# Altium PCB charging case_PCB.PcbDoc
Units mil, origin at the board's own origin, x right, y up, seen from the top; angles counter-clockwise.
Board outline 2230 x 2230 mil, 2 copper layers (Top Layer, Bottom Layer), stack 62 mil thick; 58 components, 44 nets, 186 pads, 33 vias.
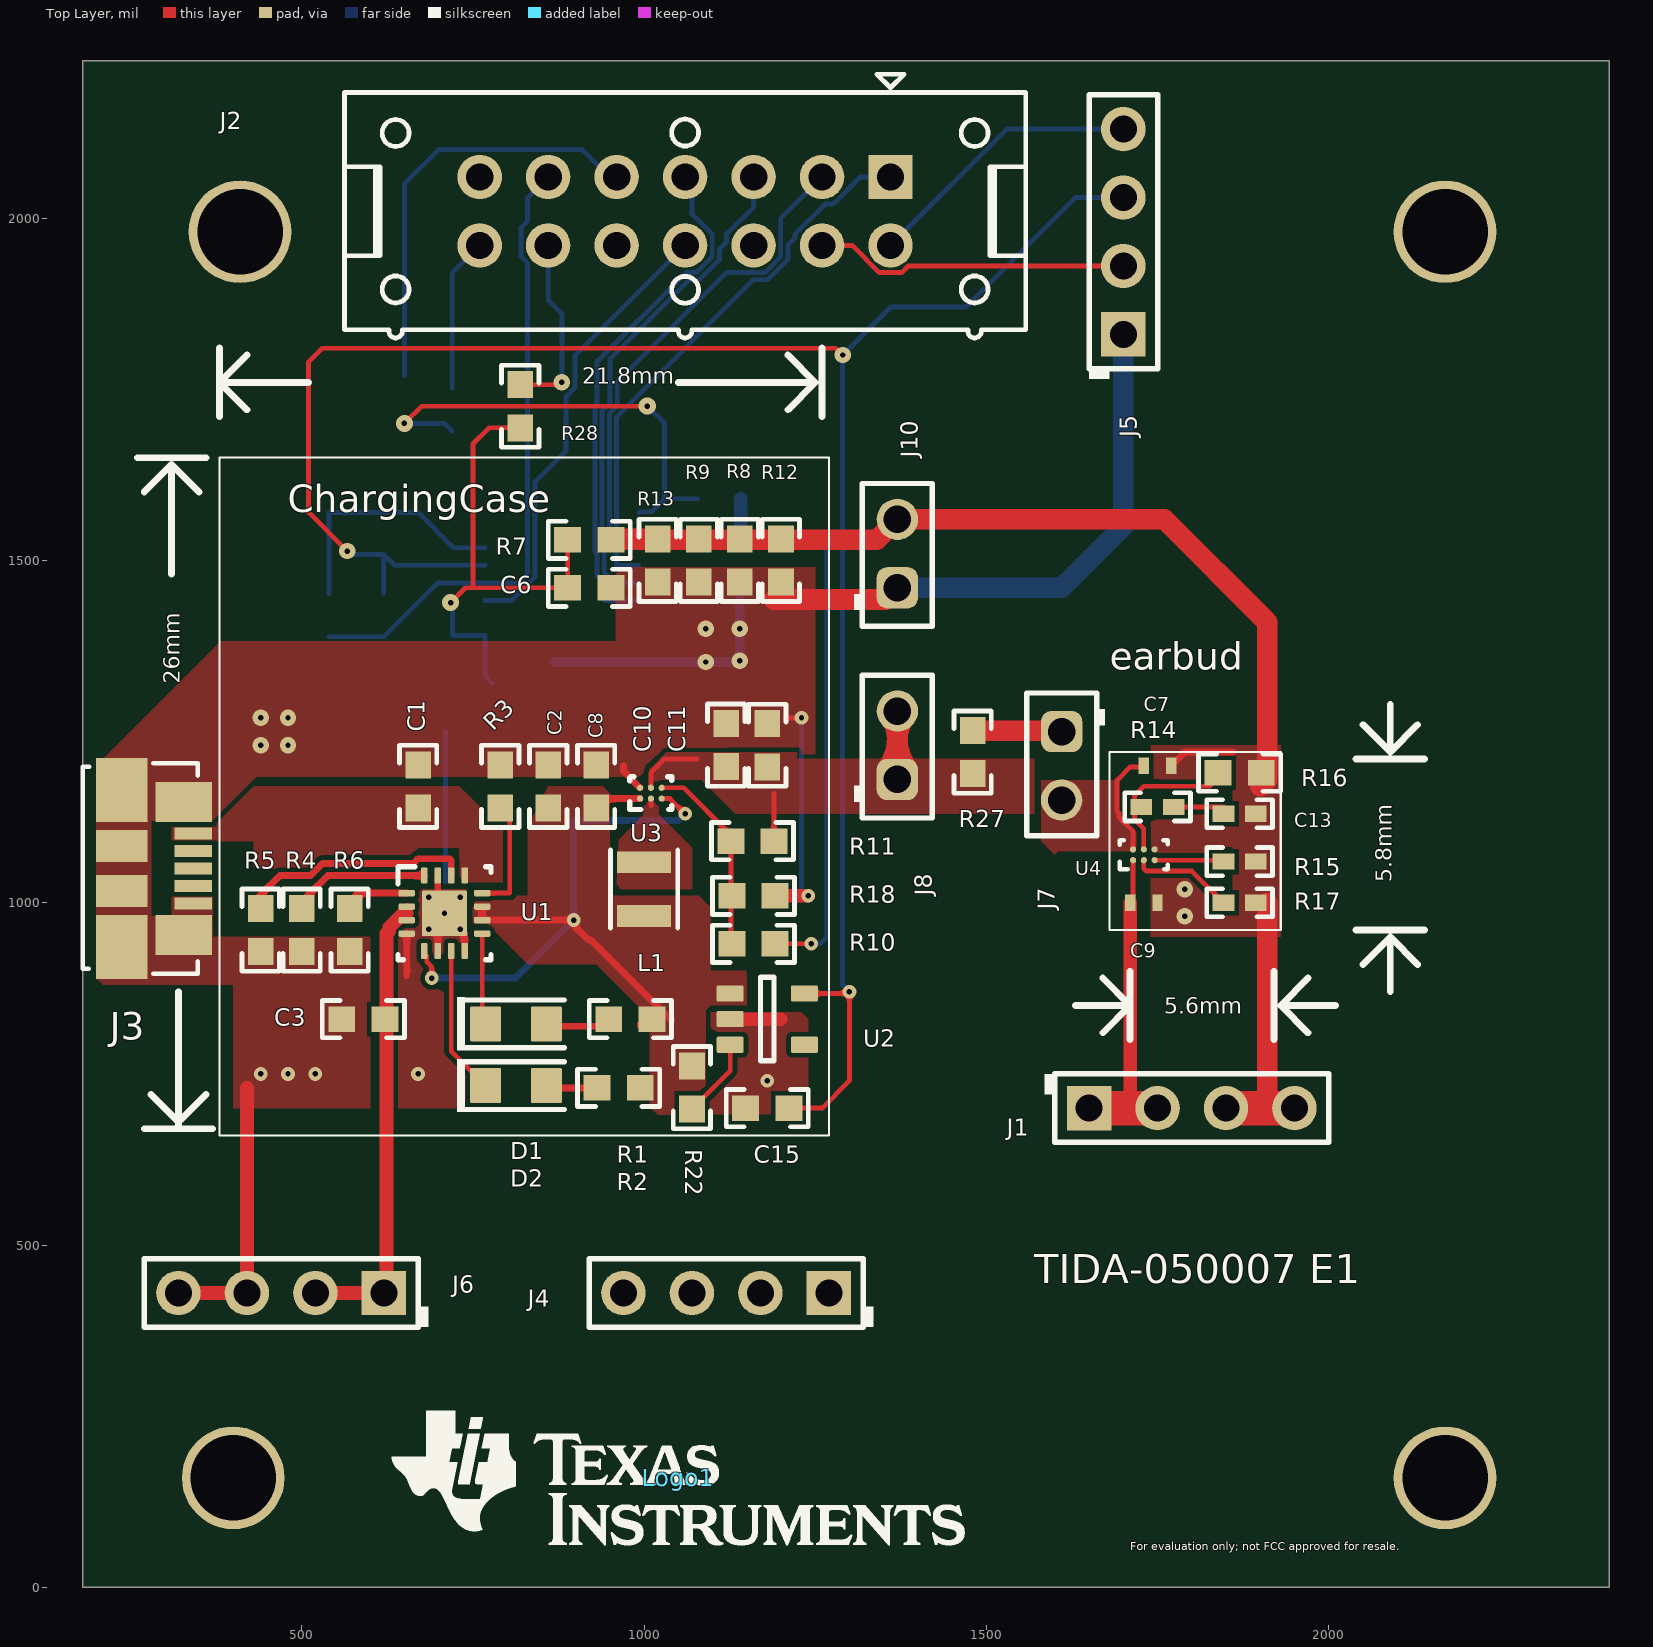
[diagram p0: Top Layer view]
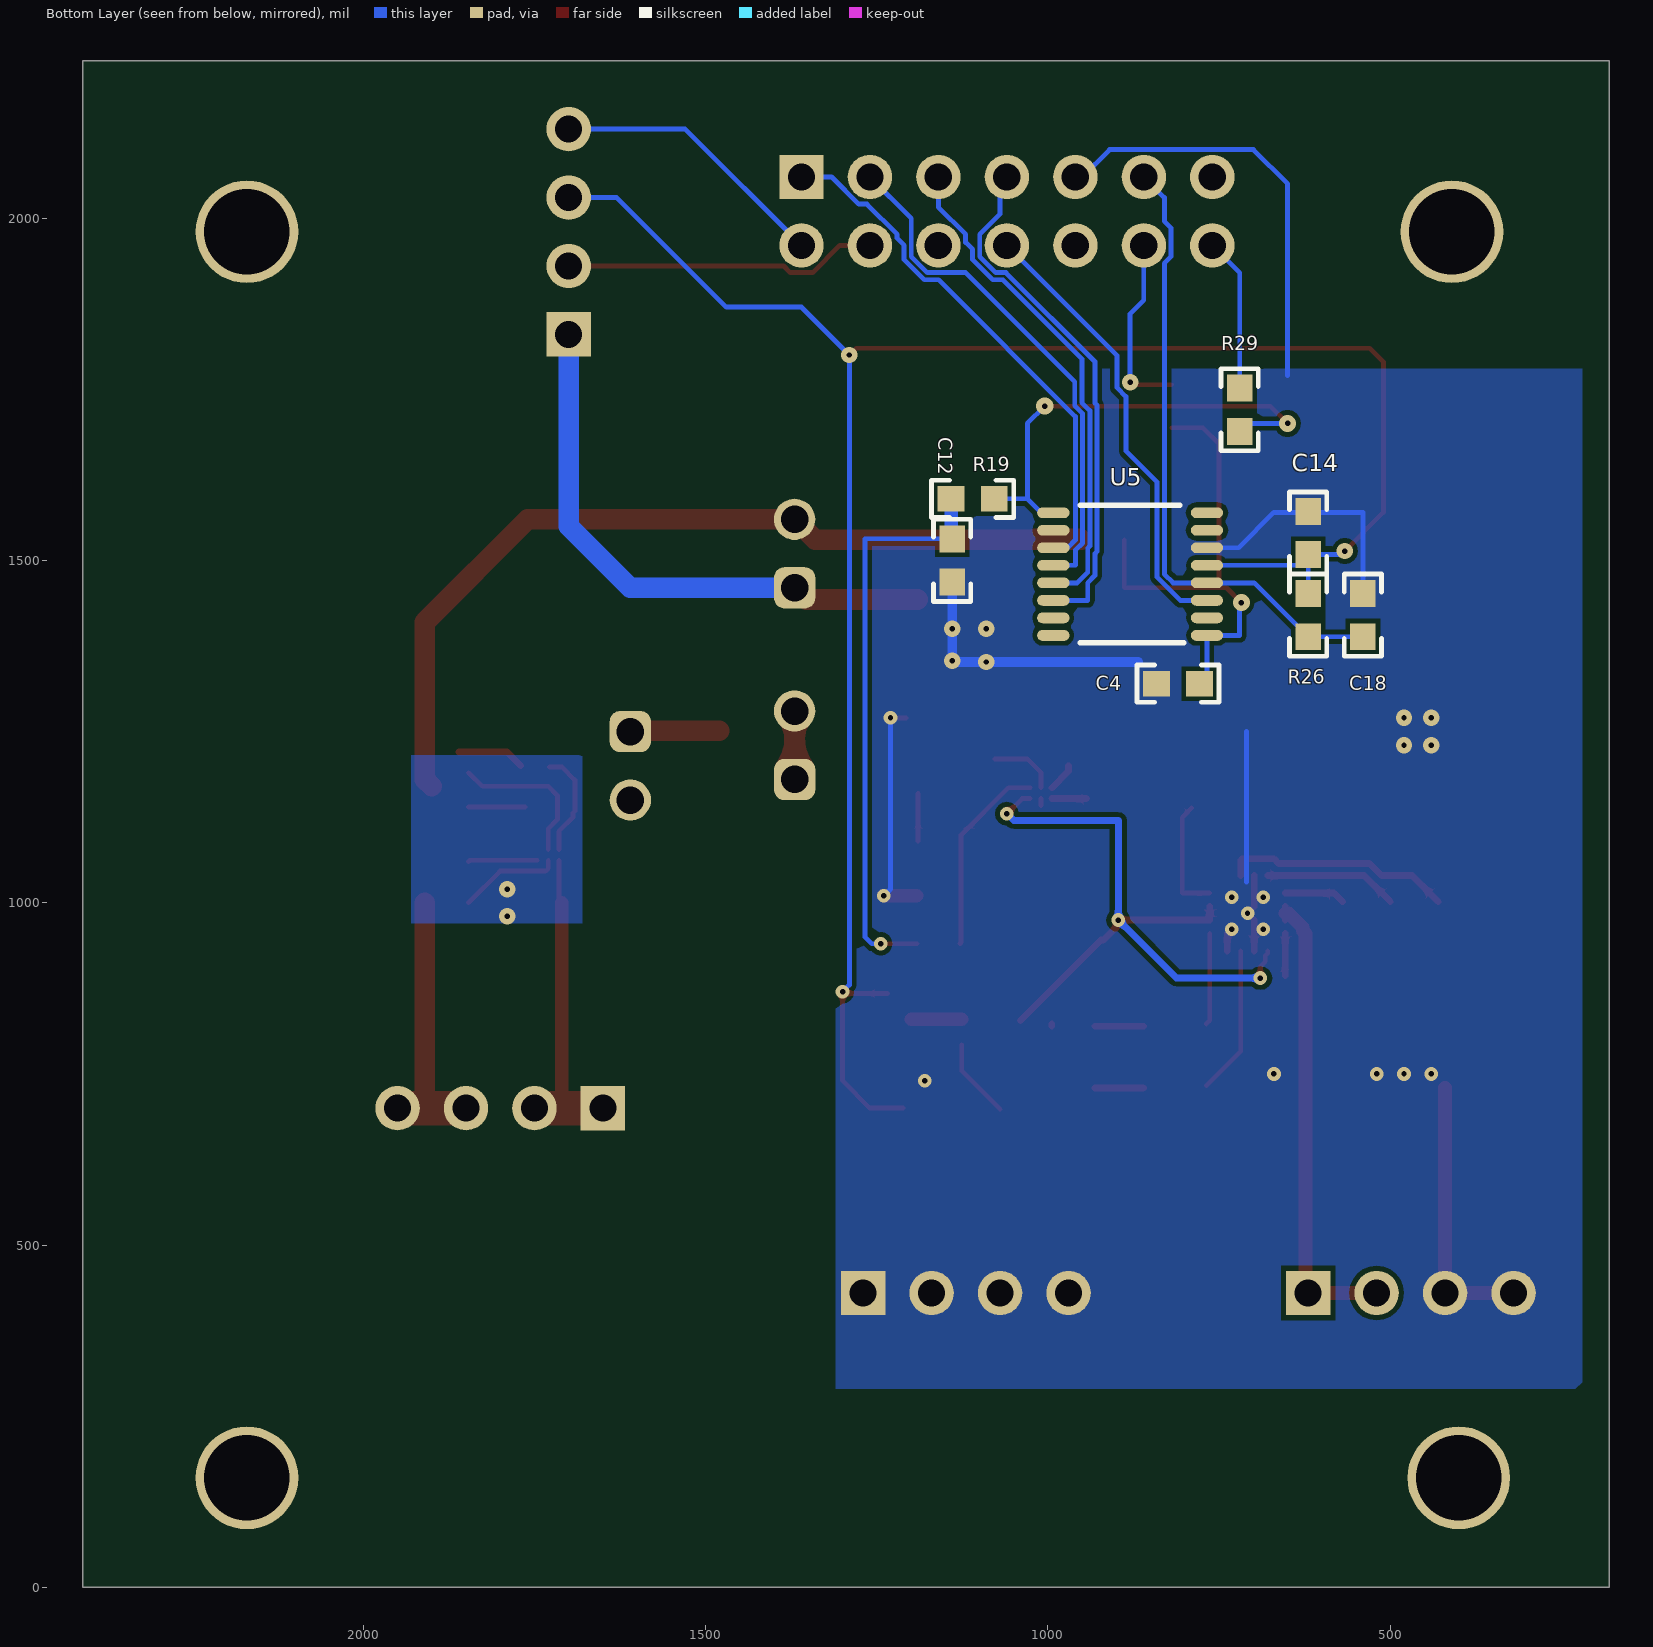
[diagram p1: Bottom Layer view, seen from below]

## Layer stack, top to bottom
Top Solder: solder mask 0.4, Solder Resist, Dk 3.5
Top Layer: signal copper 1.4
Dielectric1: core 59.2, FR-4, Dk 4.8
Bottom Layer: signal copper 1.4
Bottom Solder: solder mask 0.4, Solder Resist, Dk 3.5

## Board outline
180,0 2410,0 2410,2230 180,2230

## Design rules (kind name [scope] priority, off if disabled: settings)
AcuteAngle [All] p1: minimum=4.50000000000000E+0001 checktracksonly=FALSE
AssemblyTestPointUsage [All] p1: valid=2
Clearance Clearance_Keepouts [((IsTrack Or IsArc) And Not InPoly) And IsFree and IsKeepOut vs ((IsTrack Or IsArc) And Not InPoly) And IsFree and IsKeepOut] p1: gap=0 ignorepadtopadclearanceinfootprint=FALSE
Clearance Clearance_Poly [InPolygon] p2: gap=7 ignorepadtopadclearanceinfootprint=FALSE except(0: Arc-Hole Track-Hole SMDPad-Hole THPad-Hole Via-Hole Fill-Hole Poly-Hole Region-Hole Text-Hole)
Clearance Clearance_FiducialMark [IsKeepOut and InComponentClass('FiducialMark') vs IsPad and InComponentClass('FiducialMark')] p3: gap=0 ignorepadtopadclearanceinfootprint=FALSE
Clearance [All] p4: gap=3.6 ignorepadtopadclearanceinfootprint=FALSE except(0: Arc-Hole Track-Hole SMDPad-Hole THPad-Hole Via-Hole Fill-Hole Poly-Hole Region-Hole Text-Hole)
ComponentClearance ComponentClearance_MountingHoles_FiducialMarks [InComponentClass('Mounting Holes') vs InComponentClass('FiducialMark')] p1: gap=50 collisioncheckmode=3 verticalgap=10 showdistances=FALSE
ComponentClearance ComponentClearance_Shunt [InComponentClass('Header') vs InComponentClass('Shunt')] p2: gap=0 collisioncheckmode=3 verticalgap=0 showdistances=FALSE
ComponentClearance ComponentClearance_Logo [InComponentClass('Logo')] p3: gap=50 collisioncheckmode=3 verticalgap=10 showdistances=FALSE
ComponentClearance ComponentClearance_ScrewToNut [(HasFootprint('NY PMS 440 0025 PH')) vs (HasFootprint('Keystone_1902C'))] p4: gap=5 collisioncheckmode=3 verticalgap=10 showdistances=FALSE
ComponentClearance ComponentClearance_MountingHoles [InComponentClass('Mounting Holes')] p5: gap=250 collisioncheckmode=3 verticalgap=100000 showdistances=FALSE
ComponentClearance ComponentClearance_SmallPassives [HasFootprint('0201*') or HasFootprint('0402*') or HasFootprint('0508') or HasFootprint('0603*') or HasFootprint('0612') or HasFootprint('0805*') or HasFootprint('0815*') or HasFootprint('0830*') or HasFootprint('1206*') or HasFootprint('1210*') or HasFootprint('1808*') or HasFootprint('1812*') or HasFootprint('1825*') or HasFootprint('2010*') or HasFootprint('2220*') or HasFootprint('2225*') or HasFootprint('2512*') or HasFootprint('2728*') or HasFootprint('3518*') vs HasFootprint('0201*') or HasFootprint('0402*') or HasFootprint('0508') or HasFootprint('0603*') or HasFootprint('0612') or HasFootprint('0805*') or HasFootprint('0815*') or HasFootprint('0830*') or HasFootprint('1206*') or HasFootprint('1210*') or HasFootprint('1808*') or HasFootprint('1812*') or HasFootprint('1825*') or HasFootprint('2010*') or HasFootprint('2220*') or HasFootprint('2225*') or HasFootprint('2512*') or HasFootprint('2728*') or HasFootprint('3518*')] p6: gap=14.96 collisioncheckmode=3 verticalgap=10 showdistances=FALSE
ComponentClearance ComponentClearance_THtoSMT [IsThruComponent vs IsSMTComponent] p7: gap=40 collisioncheckmode=3 verticalgap=30 showdistances=FALSE
ComponentClearance ComponentClearance_THtoTH [IsThruComponent vs IsThruComponent] p8: gap=30 collisioncheckmode=3 verticalgap=30 showdistances=FALSE
ComponentClearance [All] p9: gap=30 collisioncheckmode=3 verticalgap=10 showdistances=FALSE
DiffPairsRouting [All] p1: maxlimit=100 minlimit=10 mostfreqgap=10 toplayer_minwidth=15 toplayer_maxwidth=15 toplayer_prefwidth=15 bottomlayer_minwidth=15 bottomlayer_maxwidth=15 bottomlayer_prefwidth=15 maxuncoupledlength=1000
FabricationTestPointUsage TestPointUsage [All] p1: valid=2 allowmultiple=FALSE
FabricationTestpoint Testpoint [All] p1: side=3 testpointundercomponent=TRUE minsize=40 maxsize=100 preferedsize=60 minholesize=0 maxholesize=40 preferedholesize=32 testpointgrid=1 allowsidetop=TRUE allowsidebottom=TRUE usegrid=TRUE gridtolerance=0.01
FanoutControl Fanout_LCC [IsLCC] p1: bgadir=Out bgaviamode=Centered fanoutstyle=Auto fanoutdirection=Alternating viagrid=1 // Fanout_LCC (Default Rule)
FanoutControl Fanout_BGA [IsBGA] p2: bgadir=Out bgaviamode=Centered fanoutstyle=Auto fanoutdirection=Alternating viagrid=1 // Fanout_BGA (Default Rule)
FanoutControl Fanout_Default [All] p4: bgadir=Out bgaviamode=Centered fanoutstyle=Auto fanoutdirection=Alternating viagrid=1 // Fanout_Default (Default Rule)
FanoutControl Fanout_Small [(CompPinCount < 5)] p5: bgadir=Out bgaviamode=Centered fanoutstyle=Auto fanoutdirection=OutThenIn viagrid=1 // Fanout_Small (Default Rule)
HoleSize [All] p1: absolutevalues=TRUE maxlimit=251 minlimit=7.87 maxpercent=80.000 minpercent=20.000
MinimumAnnularRing MinimumAnnularRing_ThermalPadVias [IsVia and InAnyComponent] p1: minimumring=5.91
MinimumAnnularRing [All] p2: minimumring=6
MinimumSolderMaskSliver MinimumSolderMaskSliver_Logo [InComponentClass('Logo') vs InComponentClass('Logo')] p1: minsoldermaskwidth=0.7
MinimumSolderMaskSliver [All] p2: minsoldermaskwidth=3.44
PlaneClearance [All] p1: clearance=0
PlaneConnect [All] p1: planeconnectstyle=Direct reliefexpansion=10 reliefentries=4 reliefconductorwidth=10 reliefairgap=10
PolygonConnect [All] p1: connectstyle=Direct reliefconductorwidth=10 reliefentries=4 polygonreliefangle="90 Angle" airgapwidth=10
RoutingVias ThermalPadVias [IsVia and InAnyComponent] p1: holewidth=7.87 width=19.68 viastyle="Through Hole" minholewidth=7.87 minwidth=19.68 maxholewidth=12.99 maxwidth=23.62
RoutingVias [All] p2: holewidth=16 width=34 viastyle="Through Hole" minholewidth=6 minwidth=20 maxholewidth=40 maxwidth=65
SilkToBoardRegionClearance [Not ((IsComment or IsDesignator) And (Hide <> 'False')) and not InRegion(1000,500,4000,800)] p1:
SilkToSilkClearance SilkToSilkClearance_Pb-FreeLogo [(HasFootprint('Pb-Free_Overlay_Medium') OR HasFootprint('Pb-Free_Overlay_Small')) vs (HasFootprint('Pb-Free_Overlay_Medium') OR HasFootprint('Pb-Free_Overlay_Small'))] p1: silktosilkclearance=0
SilkToSilkClearance [All] p2: silktosilkclearance=4
SilkToSolderMaskClearance SilkToComponentPadClearance [(IsPad or IsFill or IsRegion) and InAnycomponent] p1: minsilkscreentomaskgap=5 clearancetoexposedcopper=TRUE
SilkToSolderMaskClearance "Silk to Solder Mask Opening" [All] p2: minsilkscreentomaskgap=4 clearancetoexposedcopper=FALSE
SolderMaskExpansion [All] p1: expansion=1.97
UnpouredPolygon [All] p1: allowunpoured=TRUE
Width [All] p1: maxlimit=100 minlimit=6 preferedwidth=7 checkconnectedcopper=TRUE
13 further rules are at their usual default settings.

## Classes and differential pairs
component class Logo: Logo1
component class "charging case_EVM_Hardware": Logo1 Logo3
component class Header: J1 J4 J5 J6 J7 J8 J10

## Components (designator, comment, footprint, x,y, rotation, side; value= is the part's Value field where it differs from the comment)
C1 "GRM188Z71A106MA73D" 0603 670,1170 r90 top value=10uF
C2 "GRM188Z71A106MA73D" 0603 860.18,1170 r90 top value=10uF
C3 "GRM188Z71A106MA73D" 0603 590,830 r180 top value=10uF
C4 "GRM1885C1E102JA01D" 0603 810,1320 r0 bottom value=1000pF
C6 "06033D104KAT2A" 0603 920,1460 r180 top value=0.1uF
C7 "C1005X5R0J106M050BC" 0402_070 1750,1200 r180 top value=10uF
C8 "GRM188Z71A106MA73D" 0603 930,1170 r90 top value=10uF
C9 "C1005X5R0J106M050BC" 0402_070 1730,1000 r0 top value=10uF
C10 "06033D104KAT2A" 0603 1120,1230.2 r90 top value=0.1uF
C11 "GRM188Z71A106MA73D" 0603 1180,1230 r90 top value=10uF
C12 "06033D104KAT2A" 0603 1140,1500 r270 bottom value=0.1uF
C13 "GRM155R61E104KA87D" 0402 1870,1130 r0 top value=0.1uF
C14 "GRM188Z71A106MA73D" 0603 620,1540 r90 bottom value=10uF
C15 "GRM188Z71A106MA73D" 0603 1180,700 r180 top value=10uF
C18 "GRM1885C1E102JA01D" 0603 540,1420 r90 bottom value=1000pF
D1 "BR1112H-TR" BR1112H_Red 813,823 r180 top value=Red
D2 "BR1112H-TR" BR1112H_Red 813,733 r180 top value=Red
J1 "5-146278-4" TE_5-146278-4 1800,700 r0 top
J2 "SBH11-PBPC-D07-ST-BK" CONN_SBH11-PBPC-D07-ST-BK 1060,2010 r180 top
J3 "473460001" CONN_47346-0001 180,1050 r90 top
J4 "5-146278-4" TE_5-146278-4 1120,430 r180 top
J5 "5-146278-4" TE_5-146278-4 1700,1980 r90 top
J6 "5-146278-4" TE_5-146278-4 470,430 r180 top
J7 "TSW-102-17-G-S" Samtec_TSW-102-17-x-S 1610,1200 r270 top
J8 "TSW-102-17-G-S" Samtec_TSW-102-17-x-S 1370,1230 r90 top
J10 "TSW-102-17-G-S" Samtec_TSW-102-17-x-S 1370,1510 r90 top
L1 "DFE252012F-2R2M=P2" DFE252012C 1000,1020 r90 top value=2.2uH
Logo1 "Texas Instruments" TI_Stacked_Overlay_Small 1050,160 r0 top
Logo3 "FCC disclaimer" FCC_disclaimer 2570,120 r0 top
R1 "RT0603DRE07549RL" 0603 980,830 r180 top value=549
R2 "RT0603DRE07549RL" 0603 963,729.57 r180 top value=549
R3 "RC0603FR-073K09L" 0603 790,1170 r270 top value=3.09k
R4 "RC0603FR-074K32L" 0603 500,960 r90 top value=4.32k
R5 "RC0603FR-0756K2L" 0603 440,960 r90 top value=56.2k
R6 "RC0603FR-0710KL" 0603 570,960 r90 top value=10.0k
R7 "RG1608P-204-B-T5" 0603 920,1530 r0 top value=200k
R8 "RC0603FR-072RL" 0603 1140,1500 r270 top value=2.00
R9 "RC0603FR-072RL" 0603 1080,1500 r270 top value=2.00
R10 "RT0603DRE07255KL" 0603 1160,940 r180 top value=255k
R11 "MCT06030C1004FP500" 0603 1158.33,1090 r0 top value=1.00Meg
R12 "RC0603FR-072RL" 0603 1200,1500 r270 top value=2.00
R13 "RC0603FR-072RL" 0603 1019.76,1500 r270 top value=2.00
R14 "RC0402FR-07180KL" 0402 1750,1140 r180 top value=180k
R15 "RC0402FR-076K81L" 0402 1870,1060 r180 top value=6.81k
R16 "RC0603JR-071KL" 0603 1870,1190 r180 top value=1.0k
R17 "RC0402FR-0710KL" 0402 1870,1000 r180 top value=10.0k
R18 "RT0603DRE07348KL" 0603 1160,1010 r180 top value=348k
R19 "RC0603FR-07576KL" 0603 1110,1590 r0 bottom value=576k
R22 "RG1608P-204-B-T5" 0603 1070,730 r90 top value=200k
R26 "RT0603BRD0747K5L" 0603 620,1420 r90 bottom value=47.5k
R27 "RMCF0603ZT0R00" 0603 1480,1220 r90 top value=0
R28 "RMCF0603ZT0R00" 0603 819.29,1725.19 r90 top value=0
R29 "RMCF0603ZT0R00" 0603 720,1720 r90 bottom value=0
U1 "BQ24230RGTR" RGT0016C 708.57,984.5 r0 top
U2 "TPS7A0533PDBV" DBV0005A_N 1180,830 r0 top
U3 "TPS61099YFFR" YFF0006AFAD 1010,1160 r90 top
U4 "BQ25100AYFPR" YFP0006AFAV 1730,1070 r90 top
U5 "MSP430FR2111IPW16R" PW0016A_L 880,1480 r0 bottom

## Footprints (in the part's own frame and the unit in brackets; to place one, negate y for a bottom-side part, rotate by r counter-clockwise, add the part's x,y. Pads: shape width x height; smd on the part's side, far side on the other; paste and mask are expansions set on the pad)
0402 [mm] "0402 from SM-752 data"
  rect 0.8x0.6 smd: 1(-0.6,0) 2(0.6,0)
  silkscreen extent -1.22,-0.52 1.22,0.52, body extent -0.55,-0.3 0.55,0.3, height 0.6
0402_070 [mil] "SMD, 2-Leads, Body 1.2x0.7mm, Height 0.7mm"
  rect 15x24 smd: 1(-20,0) 2(20,0)
  body extent -24,-14 24,14, height 28
0603 [mm] "0603 from SM-752 data"
  rect 1x0.95 smd: 1(-0.8,0) 2(0.8,0)
  silkscreen extent -1.52,-0.69 1.52,0.69, body extent -0.87,-0.47 0.87,0.47, height 1
BR1112H_Red [mm] "SMD, 2-Leads, Body 2x1.25mm"
  rrect9% 1.15x1.3 smd: 1(-1.125,0) 2(1.125,0)
  silkscreen extent -1.79,-0.99 2.18,0.99, body extent -1,-0.63 1,0.62, height 0.79
CONN_47346-0001 [mm] "MOLEX"
  rect 0.45x1.38 smd: 1(1.3,-4.105) 2(0.65,-4.105) 3(0,-4.105) 4(-0.65,-4.105) 5(-1.3,-4.105)
  rect 1.475x2.1 smd: 6(-2.462,-3.755) 11(2.463,-3.75)
  rect 2.375x1.9 smd: 7(-2.912,-1.45) 10(2.912,-1.45)
  rect 1.175x1.9 smd: 8(-0.837,-1.45) 9(0.837,-1.45)
  silkscreen extent -3.9,-4.28 3.9,0, body extent -3.99,-4.43 3.99,1, height 2.72
CONN_SBH11-PBPC-D07-ST-BK [mm] "Sullins recommended land pattern"
  rect 1.65x1.65 hole 1.016 mask+0: 1(-7.62,-1.27)
  round 1.65 hole 1.016 mask+0: 2(-7.62,1.27) 3(-5.08,-1.27) 4(-5.08,1.27) 5(-2.54,-1.27) 6(-2.54,1.27) 7(0,-1.27) 8(0,1.27) 9(2.54,-1.27) 10(2.54,1.27) 11(5.08,-1.27) 12(5.08,1.27) 13(7.62,-1.27) 14(7.62,1.27)
  silkscreen extent -12.64,-5.08 12.64,4.7, body extent -12.64,-4.4 12.64,4.7, height 9.12
DBV0005A_N [mm] "SOT23, 5-Leads, Body 2.9x1.6mm, Pitch 0.95mm, Lead Span 2.8mm, IPC Medium Density"
  rrect17% 1x0.6 smd: 1(-1.375,0.95) 2(-1.375,0) 3(-1.375,-0.95) 4(1.375,-0.95) 5(1.375,0.95)
  silkscreen extent -0.25,-1.55 0.25,1.55, body extent -1.42,-1.46 1.42,1.46, height 1.09
DFE252012C [mm] "Toko"
  rect 0.8x2 smd: 1(-1,0) 2(1,0)
  silkscreen extent -1.45,-1.25 1.45,1.25, body extent -1.35,-1.1 1.35,1.1, height 1.2
FCC_disclaimer [mil]
PW0016A_L [mm] "TSOP, 16-Leads, Body 5x4.4mm, Pitch 0.65mm, IPC High Density"
  oval 1.2x0.4 smd: 1(-2.85,2.275) 2(-2.85,1.625) 3(-2.85,0.975) 4(-2.85,0.325) 5(-2.85,-0.325) 6(-2.85,-0.975) 7(-2.85,-1.625) 8(-2.85,-2.275) 9(2.85,-2.275) 10(2.85,-1.625) 11(2.85,-0.975) 12(2.85,-0.325) 13(2.85,0.325) 14(2.85,0.975) 15(2.85,1.625) 16(2.85,2.275)
  silkscreen extent -2,-2.55 1.85,2.55, body extent -3.21,-2.5 3.21,2.5, height 1
RGT0016C [mm] "QFN, 16-Leads, Body 3x3mm, Pitch 0.5mm, Thermal Pad 1.7x1.7mm, TI Recommended"
  rrect42% 0.6x0.24 smd: 1(-1.4,0.75) 2(-1.4,0.25) 3(-1.4,-0.25) 4(-1.4,-0.75) 9(1.4,-0.75) 10(1.4,-0.25) 11(1.4,0.25) 12(1.4,0.75)
  rrect42% 0.24x0.6 smd: 5(-0.75,-1.4) 6(-0.25,-1.4) 7(0.25,-1.4) 8(0.75,-1.4) 13(0.75,1.4) 14(0.25,1.4) 15(-0.25,1.4) 16(-0.75,1.4)
  rrect6% 1.55x1.55 on Top Paste: 17(0,0)
  rrect6% 1.68x1.68 smd paste-0.85: 17(0,0)
  silkscreen extent -1.72,-1.72 1.73,1.73, body extent -1.5,-1.5 1.5,1.5, height 1
Samtec_TSW-102-17-x-S [mm] "Header, 2.54mm, 2x1, TH"
  rrect50% 1.53x1.53 hole 1.02: 1(-1.27,0)
  round 1.53 hole 1.02: 2(1.27,0)
  silkscreen extent -2.7,-1.3 2.6,1.6, body extent -2.67,-1.27 2.54,1.27, height 18.29
TE_5-146278-4 [mm] "TE CONNECTIVITY"
  rect 1.65x1.65 hole 1: 1(-3.81,0)
  round 1.65 hole 1: 2(-1.27,0) 3(1.27,0) 4(3.81,0)
  silkscreen extent -5.46,-1.27 5.08,1.27, body extent -4.95,-1.17 4.95,1.17, height 8.13
TI_Stacked_Overlay_Small [mil]
  silkscreen extent -418,-98 418,98
YFF0006AFAD [mm] "DSBGA, 6-Leads, Body 1.226x 0.884mm, Pitch 0.4mm"
  round 0.23 smd paste-0.13 mask+0.038: A1(-0.2,0.4) A2(0.2,0.4) B1(-0.2,0) B2(0.2,0) C1(-0.2,-0.4) C2(0.2,-0.4)
  silkscreen extent -0.61,-0.78 0.61,0.78, body extent -0.46,-0.63 0.46,0.63, height 0.63
YFP0006AFAV [mm] "TI DSBGA 0.88x1.58mm"
  round 0.23 smd paste-0.13 mask+0.038: A1(-0.2,0.4) A2(0.2,0.4) B1(-0.2,0) B2(0.2,0) C1(-0.2,-0.4) C2(0.2,-0.4)
  silkscreen extent -0.53,-0.89 0.53,0.89, body extent -0.46,-0.8 0.46,0.81, height 0.51

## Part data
C1 C2 C3 C8 C11 C14 C15: library part CMP-0007497-5, "CAP, CERM, 10 uF, 10 V, +/- 20%, X7R, 0603", Cap_Case=0603, Manufacturer=MuRata, Supplier Part Number 1=81-GRM188Z71A106MA3D, TempCo=X7R, Tolerance_%=20%, Value1=Unknown, Value2=10V, ValueDisplayed=10uF
C4 C18: library part CMP-0007159-4, "CAP, CERM, 1000 pF, 25 V, +/- 5%, C0G/NP0, 0603", Cap_Case=0603, Manufacturer=MuRata, Supplier Part Number 1=GRM1885C1E102JA01D-ND, TempCo=C0G/NP0, Tolerance_%=5%, Value1=Unknown, Value2=25V, ValueDisplayed=1000pF
C6 C10 C12: library part CMP-0006758-5, "CAP, CERM, 0.1 uF, 25 V, +/- 10%, X5R, 0603", Cap_Case=0603, Manufacturer=AVX, Supplier Part Number 1=478-1244-1-ND, TempCo=X5R, Tolerance_%=10%, Value1="0.048 ohm", Value2=25V, ValueDisplayed=0.1uF
C7 C9: library part CMP-0006257-2, "CAP, CERM, 10 uF, 6.3 V, +/- 20%, X5R, 0402", Cap_Case=0402_070, Manufacturer=TDK, Supplier Part Number 1=445-8920-1-ND, TempCo=X5R, Tolerance_%=20%, Value1="0.003019 ohm", Value2=6.3V, ValueDisplayed=10uF
C13: library part CMP-0006607-2, "CAP, CERM, 0.1 uF, 25 V, +/- 10%, X5R, 0402", Cap_Case=0402, Manufacturer=MuRata, Supplier Part Number 1=490-5920-1-ND, TempCo=X5R, Tolerance_%=10%, Value1=Unknown, Value2=25V, ValueDisplayed=0.1uF
D1 D2: library part CMP-0067678-1, "LED, Red, SMD", Color=Red, Manufacturer="Stanley Electric Co., LTD", Power_TotalModule=57.5mW, Supplier Part Number 1=404-1017-1-ND, Value1=0.0575W, Value2=1.7V
J1 J4 J5 J6: library part CMP-0054950-1, "Header, 100mil, 4x1, Tin, TH", Manufacturer="TE Connectivity", Supplier Part Number 1=5-146278-4-ND
J2: library part CMP-0054695-1, "Header (shrouded), 100 mil, 7x2, Gold, TH", Manufacturer="Sullins Connector Solutions", Supplier Part Number 1=S9170-ND
J3: library part CMP-0055296-1, "Connector, Receptacle, Micro-USB Type B, R/A, Bottom Mount SMT", Manufacturer=Molex, Supplier Part Number 1=WM17141CT-ND
J7 J8 J10: library part CMP-0077742-1, "Header, 2.54mm, 2x1, Gold, TH", Color=Black, Manufacturer=Samtec, Supplier Part Number 1=SAM1061-02-ND
L1: library part CMP-0058932-1, "Inductor, Shielded, Powdered Iron, 2.2 uH, 2.3 A, 0.082 ohm, SMD", Manufacturer="MuRata Toko", PartNumber=DFE252012F-2R2M{}P2, Supplier Part Number 1=490-13055-1-ND, Value1="0.082 ohm", Value2=2.3A, ValueDisplayed=2.2uH
Logo1: library part CMP-0074838-1, "Texas Instrument Corporate Signature"
Logo3: library part CMP-0074847-1, "FCC_disclaimer"
R1 R2: library part CMP-0025400-3, "RES, 549, 0.5%, 0.1 W, 0603", Manufacturer="Yageo America", Power_W=100mW, TempCo="50 ppm/C", Tolerance_%=0.5%, Value2=0.1W, Value_Code=549R, ValueDisplayed=549
R3: library part CMP-0023077-3, "RES, 3.09 k, 1%, 0.1 W, 0603", Manufacturer="Yageo America", Power_W=100mW, Supplier Part Number 1=311-3.09KHRCT-ND, TempCo="200 ppm/C", Tolerance_%=1%, Value2=0.1W, Value_Code=3k09, ValueDisplayed=3.09k
R4: library part CMP-0023147-3, "RES, 4.32 k, 1%, 0.1 W, 0603", Manufacturer="Yageo America", Power_W=100mW, Supplier Part Number 1=311-4.32KHRCT-ND, TempCo="200 ppm/C", Tolerance_%=1%, Value2=0.1W, Value_Code=4k32, ValueDisplayed=4.32k
R5: library part CMP-0023186-3, "RES, 56.2 k, 1%, 0.1 W, 0603", Manufacturer="Yageo America", Power_W=100mW, Supplier Part Number 1=311-56.2KHRCT-ND, TempCo="200 ppm/C", Tolerance_%=1%, Value2=0.1W, Value_Code=56k2, ValueDisplayed=56.2k
R6: library part CMP-0022746-3, "RES, 10.0 k, 1%, 0.1 W, 0603", Manufacturer="Yageo America", Power_W=100mW, Supplier Part Number 1=311-10.0KHRCT-ND, TempCo="200 ppm/C", Tolerance_%=1%, Value2=0.1W, Value_Code=10k0, ValueDisplayed=10.0k
R7 R22: library part CMP-0023465-3, "RES, 200 k, 0.1%, 0.1 W, 0603", Manufacturer="Susumu Co Ltd", Power_W=100mW, Supplier Part Number 1=RG16P200KBCT-ND, TempCo="25 ppm/C", Tolerance_%=0.1%, Value2=0.1W, Value_Code=200k
R8 R9 R12 R13: library part CMP-0023011-4, "RES, 2.00, 1%, 0.1 W, 0603", Manufacturer=Yageo, Power_W=100mW, Supplier Part Number 1=311-2.00HRCT-ND, TempCo="200 ppm/C", Tolerance_%=1%, Value2=0.1W, Value_Code=2R00, ValueDisplayed=2.00
R10: library part CMP-0024989-3, "RES, 255 k, 0.5%, 0.1 W, 0603", Manufacturer="Yageo America", Power_W=100mW, TempCo="50 ppm/C", Tolerance_%=0.5%, Value2=0.1W, Value_Code=255k
R11: library part CMP-0022731-2, "RES, 1.00 M, 1%, 0.125 W, 0603", Manufacturer=Vishay/Beyschlag, Power_W=125mW, Supplier Part Number 1=MCT0603-1.00M-CFCT-ND, TempCo="50 ppm/C", Tolerance_%=1%, Value2=0.125W, Value_Code=1M00, ValueDisplayed=1.00M
R14: library part CMP-0026723-1, "RES, 180 k, 1%, 0.063 W, 0402", Manufacturer="Yageo America", Power_W=63mW, Supplier Part Number 1=311-180KLRCT-ND, TempCo="100 ppm/C", Tolerance_%=1%, Value2=0.063W, Value_Code=180k
R15: library part CMP-0078787-1, "RES, 6.81 k, 1%, 0.063 W, 0402", Manufacturer="Yageo America", Power_W=63mW, Supplier Part Number 1=311-6.81KLRCT-ND, TempCo="100 ppm/C", Tolerance_%=1%, Value2=0.063W, Value_Code=6k81, ValueDisplayed=6.81k
R16: library part CMP-0025899-5, "RES, 1.0 k, 5%, 0.1 W, 0603", Manufacturer=Yageo, Power_W=100mW, Supplier Part Number 1=311-1.0KGRCT-ND, TempCo="100 ppm/C", Tolerance_%=5%, Value2=0.1W, Value_Code=1k00, ValueDisplayed=1.0k
R17: library part CMP-0078669-1, "RES, 10.0 k, 1%, 0.063 W, 0402", Manufacturer="Yageo America", Power_W=63mW, Supplier Part Number 1=311-10.0KLRCT-ND, TempCo="100 ppm/C", Tolerance_%=1%, Value2=0.063W, Value_Code=10k0, ValueDisplayed=10.0k
R18: library part CMP-0025159-3, "RES, 348 k, 0.5%, 0.1 W, 0603", Manufacturer="Yageo America", Power_W=100mW, TempCo="50 ppm/C", Tolerance_%=0.5%, Value2=0.1W, Value_Code=348k
R19: library part CMP-0023189-2, "RES, 576 k, 1%, 0.1 W, 0603", Manufacturer="Yageo America", Power_W=100mW, Supplier Part Number 1=311-576KHRCT-ND, TempCo="200 ppm/C", Tolerance_%=1%, Value2=0.1W, Value_Code=576k
R26: library part CMP-0024266-3, "RES, 47.5 k, 0.1%, 0.1 W, 0603", Manufacturer="Yageo America", Power_W=100mW, TempCo="25 ppm/C", Tolerance_%=0.1%, Value2=0.1W, Value_Code=47k5, ValueDisplayed=47.5k
R27 R28 R29: library part CMP-0023343-3, "RES, 0, 1%, 0.1 W, AEC-Q200 Grade 0, 0603", Manufacturer="Stackpole Electronics Inc", Power_W=100mW, Supplier Part Number 1=RMCF0603ZT0R00CT-ND, TempCo=ppm/C, Tolerance_%=1%, Value2=0.1W, Value_Code=0
U1: library part CMP-0034120-2, "USB Friendly 0.5 A Li+ Charger with Dynamic Power Management, 6.6 V OVP, 4.3 V, -40 to 85 degC, 16-pin QFN (RGT), Green (RoHS & no Sb/Br)", Manufacturer="Texas Instruments", Over Voltage Protection=N, PartNumber=BQ24073RGTR
U2: library part CMP-0013051-2, "1uA IQ, 200 mA, Ultralow IQ Low-Dropout Regulator, DBV0005A (SOT-5)", Alternate Manufacturer="Texas Instruments"
U3: library part CMP-0074075-1, "Synchronous Boost Converter with 800 nA Ultra-Low Quiescent Current, YFF0006AFAD (DSBGA-6)", Alternate Manufacturer="Texas Instruments", Alternate PartNumber=TPS61099YFFT
U4: library part CMP-0076143-1, "250-mA Single Cell Li-Ion Battery Charger, 1mA termination, 75nA Battery leakage, YFP0006AFAV (DSBGA-6)", Alternate Manufacturer="Texas Instruments", Alternate PartNumber=BQ25100AYFPT
U5: library part CMP-0076600-1, "16 MHz Ultra-Low-Power Microcontroller With 4 KB FRAM, 1 KB SRAM, 12 IO, 8 ch ADC10, PW0016A (TSSOP-16)", Alternate Manufacturer="Texas Instruments", Alternate PartNumber=MSP430FR2111IPW16

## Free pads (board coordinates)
  round 150 hole 125: 1(400,160) 1(410,1980) 1(2170,160) 1(2170,1980)

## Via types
v1: diameter 24, hole 8, Top Layer to Bottom Layer, 13 vias
v2: diameter 20, hole 8, Top Layer to Bottom Layer, 12 vias
v3: diameter 19.68, hole 7.87, Top Layer to Bottom Layer, 5 vias
v4: diameter 25, hole 8, Top Layer to Bottom Layer, 3 vias

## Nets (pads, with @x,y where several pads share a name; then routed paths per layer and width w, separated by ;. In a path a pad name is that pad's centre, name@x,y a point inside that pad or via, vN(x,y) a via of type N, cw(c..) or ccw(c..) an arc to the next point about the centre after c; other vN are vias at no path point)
BOOST_IN: C2.1 C8.1 L1.1 R1.1 R2.1 R22.2 U1.5 U1.10 U1.11 U2.1 U3.A1 U3.C1 | length 1059.8
  Top Layer w7: U1.5 679.04,925.91 682.62,922.33 682.62,914.03 690,906.65 v2(690,890) ; U3.C1 1037.87,1152.13 v2(1060,1130)
  Top Layer w10: U1.11 U1.10 v2(897.23,974.66) 898.57,976 898.57,966 919,945.57 922.6,945.57 1040.06,828.1 ; C8.1@943.62,1152.13 U3.A1 ; R1.1@994.5,819.57 R1.1@994.5,823.18
  Bottom Layer w10: v2(690,890) 812.57,890 v2(897.23,974.66) 897.23,1119.97 1049.97,1119.97 v2(1060,1130)
DVCC: C14.1 C15.1 J5.3 R26.2 U2.5 U5.5 | length 3100.6
  Top Layer w7: v1(566.3,1513.7) 510,1570 510,1790 530,1810 1280,1810 v1(1290,1800) ; C15.1 1260,700 1300,740 v2(1300,870) 1297.4,867.4 U2.5
  Bottom Layer w7: v1(566.3,1513.7) 571.5,1508.5 C14.1 ; R26.2 C14.1 ; U5.5 635.71,1492.8 C14.1 ; v2(1300,870) 1290,880 v1(1290,1800) 1360,1870 1470,1870 1630,2030 J5.3
FB_CTRL: R19.1 R29.1 U5.9 | length 680.5
  Top Layer w7: v4(650,1700) 675.29,1725.29 v4(1004.71,1725.29)
  Bottom Layer w7: v4(650,1700) 708.5,1700 R29.1 ; U5.9 993.65,1571.01 1011.01,1571.01 1030,1590 ; v4(1004.71,1725.29) 1030,1700 1030,1590 ; R19.1 1030,1590
GND: C1.2 C2.2 C3.2 C4.2 C6.1 C8.2 C10.2 C11.2 C12.2 C14.2 C15.2 C18.2 J2.9 J3.5 J3.6 J3.7 J3.8 J3.9 J3.10 J3.11 J4.1 J4.2 J4.3 J4.4 J5.1 J6.3 J6.4 J10.1 R3.1 R4.1 R5.1 R6.1 R8.2 R9.2 R12.2 R13.2 R18.1 U1.4 U1.6 U1.8 U1.15 U1.17@708.57,984.5 U2.2 U3.A2 U5.6 | length 3479.9
  Top Layer w7: 1207.2,1270 v2(1230,1270)
  Top Layer w10: 653.45,893.45 U1.4 ; U1.6 U1.17@698.72,974.66 ; U1.15 698.72,994.35 v3(708.57,984.5) ; U1.8 U1.17@738.09,954.98 ; 970,1200 970,1192.13 U3.A2
  Top Layer w20: J6.4 J6.3 420,730 ; U2.2 1199.68,830 ; R18.1 v2(1240,1010)
  Top Layer w30: 1190,1442.91 1352.91,1442.91 J10.1
  Bottom Layer w7: C18.2 540,1570 670.07,1570 721.68,1518.39 U5.6 ; 650,1770 650,2050 700,2100 910,2100 950,2060 J2.9 ; 710,1030 710,1250 ; v2(1230,1270) 1230,1020 v2(1240,1010)
  Bottom Layer w14: 868.39,1351.61 1138.39,1351.61 v1(1140,1353.23) C12.2
  Bottom Layer w30: J10.1 1610,1460 1700,1550 J5.1
  other v1: 440,1230 480,1230 440,1270 480,1270 1090,1351.61 1090,1400 1140,1400
  other v2: 1180,740 440,750 480,750 520,750 670,750
  other v3: 685.34,961.28 731.79,961.28 685.34,1007.73 731.79,1007.73
IOUT_S: C4.1 C6.2 R7.1 R28.1 U5.1 | length 710.3
  Top Layer w7: v4(717.61,1438.37) 739.24,1460 750,1460 ; R28.1 773.69,1693.69 750,1670 750,1460 ; R7.1 C6.2 750,1460
  Bottom Layer w7: v4(717.61,1438.37) 720.43,1435.54 720.43,1390.43 U5.1 767.8,1330.71 C4.1
NetC3_1: C3.1 J6.1 J6.2 U1.2 U1.3 | length 691
  Top Layer w10: U1.3 653.45,984.5 U1.2
  Top Layer w20: J6.2 J6.1 624,434 624,955.06 628.04,959.09 628.04,964.17 648.37,984.5 653.45,984.5
NetC7_2: C7.2 J7.2 U4.A2 | length 156.3
  Top Layer w7: U4.A2 1714.25,1104.53 1693.53,1125.25 1693.53,1131.01 1690.85,1133.69 1690.85,1179.15 1710,1198.29 C7.2@1728.29,1198.29
NetC10_1: C10.1 C11.1 J8.1 J8.2 R11.2 R27.1 U3.B2 | length 267.7
  Top Layer w7: U3.B2 1010,1190 1030,1210 1077.2,1210 ; R11.2 1189.82,1159.82 1190,1160
  Top Layer w30: J8.1 J8.2
NetC12_1: C12.1 R10.1 R19.2 | length 847.5
  Top Layer w7: R10.1 v2(1244.09,940)
  Bottom Layer w7: C12.1 1267.05,1531.5 1267.05,949.72 1257.32,940 v2(1244.09,940)
  Bottom Layer w20: C12.1 1141.5,1532.99 R19.2
NetC13_1: C13.1 R14.1 | length 82.8
  Top Layer w7: R14.1@1763.62,1140 C13.1@1846.38,1140
NetD1_1: D1.1 R1.2 | length 70.8
  Top Layer w10: D1.1@860.72,819.57 R1.2@931.5,819.57
NetD1_2: D1.2 U1.9 | length 134.1
  Top Layer w7: U1.9 763.68,828.03 D1.2
NetD2_1: D2.1 R2.2 | length 70.8
  Top Layer w10: D2.1@860.72,729.57 R2.2
NetD2_2: D2.2 U1.7 | length 217.2
  Top Layer w7: U1.7 718.41,783.3 D2.2
NetJ2_2: J2.2 J5.4 | length 410.4
  Bottom Layer w7: J2.2 1530,2130 J5.4
NetJ2_4: J2.4 J5.2 | length 460.4
  Top Layer w7: J2.4 1304.03,1960 1343.61,1920.42 1376.39,1920.42 1385.97,1930 J5.2
NetJ2_12: J2.12 R28.2 | length 298.6
  Top Layer w7: R28.2 876.68,1756.68 v1(880,1760)
  Bottom Layer w7: v1(880,1760) 880,1860 860,1880 J2.12 J2.12@880,1940
NetJ2_14: J2.14 R29.2 | length 225.1
  Bottom Layer w7: R29.2 720,1920 J2.14
NetJ7_1: J7.1 R27.2 | length 130.6
  Top Layer w30: R27.2 1608.5,1251.5 J7.1
NetL1_2: L1.2 U3.B1 | length 10.1
  Top Layer w7: 1010,1142.01 U3.B1
NetR3_2: R3.2 U1.12 | length 170.6
  Top Layer w7: U1.12 804.03,1014.03 804.03,1124.47 R3.2
NetR4_2: R4.2 U1.16 | length 194.8
  Top Layer w10: R4.2@500,1001.5 538.13,1039.62 U1.16
NetR5_2: R5.2 U1.14 | length 337.8
  Top Layer w10: R5.2@430,1001.5 468.13,1039.62 512.85,1039.62 530.72,1057.5 663.33,1057.5 670.14,1064.31 716.17,1064.31 718.41,1062.07 U1.14
NetR6_2: R6.2 U1.1 | length 88.6
  Top Layer w10: R6.2@570,1001.5 582.54,1014.03 U1.1
NetR10_2: R10.2 R11.1 R18.2 U3.C2 | length 289.3
  Top Layer w7: U3.C2 1057.87,1167.87 1126.83,1098.92 R11.1 1126.83,941.67 R10.2
NetR14_2: R14.2 R16.2 U4.B2 | length 228.1
  Top Layer w7: U4.B2 1730,1108.35 1716.38,1121.97 1716.38,1140 1716.38,1156.38 1730,1170 1826.38,1170 R16.2@1846.38,1190
NetR15_2: R15.2 U4.C1 | length 101.3
  Top Layer w7: U4.C1@1745.9,1061.97 1844.41,1061.97 R15.2
NetR17_2: R17.2 U4.B1 | length 149.2
  Top Layer w7: U4.B1 1730,1050 1733.78,1046.22 1800.15,1046.22 R17.2
NetR22_1: R22.1 U2.3 | length 117.2
  Top Layer w7: R22.1 1125.87,754.37 U2.3
P1.0: U5.2
P1.2: U5.16
P1.3: U5.15
P1.4: J2.7 U5.14 | length 770.5
  Bottom Layer w7: U5.14 941.97,1441.61 941.97,1467.49 931.3,1478.15 931.3,1510 928.2,1513.1 928.2,1726.3 931.3,1729.4 931.3,1790.32 1061.4,1920.42 1076.39,1920.42 1099.58,1943.61 1099.58,1976.39 1070,2005.97 1070,2050 J2.7
P1.5: J2.5 U5.13 | length 735.8
  Bottom Layer w7: U5.13 957.24,1467.2 941.9,1482.54 941.9,1517.94 938.8,1521.04 938.8,1718.8 950.42,1730.42 950.42,1794.44 1065.79,1909.82 1080.79,1909.82 1110.18,1939.21 1110.18,1954.21 1120.42,1964.44 1120.42,1976.39 1160,2015.97 J2.5
P1.6: J2.3 U5.12 | length 765.5
  Bottom Layer w7: U5.12 959.6,1492.8 959.6,1515.24 949.4,1525.43 949.4,1714.41 961.02,1726.03 961.02,1761.02 1120.42,1920.42 1176.39,1920.42 1199.58,1943.61 1199.58,1999.58 J2.3
P1.7: J2.1 U5.11 | length 777.9
  Bottom Layer w7: U5.11 971.44,1518.39 960,1529.82 960,1710.02 1159.8,1909.82 1180.79,1909.82 1210.18,1939.21 1210.18,1960.2 1220.42,1970.44 1220.42,1976.39 1264.44,2020.42 1276.39,2020.42 1315.97,2060 J2.1
P2.0: U5.10
P2.6: U5.8
P2.7: U5.7
RST: C18.1 J2.11 R26.1 U5.4 | length 928.3
  Bottom Layer w7: C18.1 R26.1 698.7,1467.2 U5.4 817.2,1467.2 830,1480 830,1934.03 820.42,1943.61 820.42,1985.97 830,1995.56 830,2030 J2.11
TEST: J2.8 U5.3 | length 662.2
  Bottom Layer w7: U5.3 806.6,1441.61 840.6,1475.61 840.6,1614.39 886.21,1660 886.21,1739.2 899.1,1752.09 899.1,1799.1 J2.8
USB+: C1.1 J3.1 U1.13
VBAT: C9.1 J1.1 J1.2 U4.A1 | length 463.9
  Top Layer w7: C9.1 1714.25,1004.25 U4.A1
  Top Layer w20: 1710,700 C9.1
  Top Layer w50: J1.1 1710,700 J1.2
VSS: C7.1 C9.2 C13.2 J1.3 J1.4 J10.2 R7.2 R8.1 R9.1 R12.1 R13.1 R15.1 R16.1 R17.1 U4.C2 | length 1844.4
  Top Layer w10: C7.1 1790,1220 1860,1220
  Top Layer w30: R13.1 952.99,1531.5 R7.2 1340,1530 J10.2 1760,1560 1910,1410 1910,1180 1900,1170 ; 1910,700 1910,1000
  Top Layer w50: J1.3 1910,700 J1.4
  other v1: 1790,980 1790,1020
pads on no net: J2.6 J2.10 J2.13 J3.2 J3.3 J3.4 U1.17@708.57,984.5 U2.4

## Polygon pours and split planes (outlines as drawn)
VSS on Top Layer "VSS_L01_P126" (solid, remove dead copper, pour order 126): 1740,1040 1740,950 1930,950 1930,1230 1740,1230 1740,1170 1820,1170 1820,1210 1860,1210 1860,990 1822,990 1822,1039.5 1821.5,1040
GND on Top Layer "GND_L01_P116" (solid, remove dead copper, pour order 116): 310,1010 310,950 380,950 370,960 370,1010
GND on Top Layer "GND_L01_P112" (solid, remove dead copper, pour order 112): 1090,900 1090,681.46 1099.86,691.32 1240,691.32 1240,830 1230,840 1097.32,840
GND on Top Layer "GND_L01_P108" (solid, remove dead copper, pour order 108): 740,1020 740,700 640,700 640,1013.44 646.56,1020
GND on Top Layer "GND_L01_P106" (solid, remove dead copper, pour order 106): 340,960 350,950 600,950 600,700 400,700 400,880 330,880 330,950
NetC7_2 on Top Layer "TOP_LAYER_NETC7_2_P076" (solid, remove dead copper, pour order 76): 1580,1180 1580,1090 1600,1070 1604.92,1074.92 1719.17,1074.92 1719.17,1105.37 1690.85,1133.69 1690.85,1179.15 1580.85,1179.15
VSS on Top Layer "TOP_LAYER_VSS_P074" (solid, remove dead copper, pour order 74): 1742.8,1072.95 1745.75,1070 1818.35,1070 1830,1081.65 1870,1081.65 1870,960 1930,960 1930,1230 1860,1230 1860,1128.19 1740,1128.19 1740,1075.75 1740.83,1074.92
USB+ on Top Layer "TOP_LAYER_USB+_P012" (solid, remove dead copper, pour order 12): 435.63,1120 435.63,1054.37 440,1050 510,1050 530,1070 660,1070 670,1080 730,1080 730,1030 800,1030 800,1100 730,1170 500,1170 500,1155.63 464.37,1120 435.63,1120 435.63,1054.37 440,1050
BOOST_IN on Top Layer "TOP_LAYER_BOOST_IN_P016" (solid, remove dead copper, pour order 16): 950,1160 950,1010 1080,1010 1097.32,992.68 1097.32,900.87 1149.13,900.87 1150,886.93 1150,880 1150,850 1097.32,850 1090,842.68 1090,690 1020,690 1008.57,701.43 1008.57,840 1000,840 930,910 830,910 770,970 750,970 750,1010 830,1010 830,1111.18 860.18,1170 940,1170
NetL1_2 on Top Layer "TOP_LAYER_NETL1_2_P018" (solid, remove dead copper, pour order 18): 999.85,1155.08 999.85,1129.17 962.92,1092.24 959.53,1020 1070.68,1020 1070.68,1080 1020.68,1130 1021.51,1130.83 1021.51,1155.08
NetC10_1 on Top Layer "TOP_LAYER_NETC10_2_P032" (solid, remove dead copper, pour order 32): 1008.45,1164.62 1023.53,1179.7 1083.39,1179.7 1133.37,1129.71 1223.37,1129.7 1223.37,1219.7 1034.07,1219.7 1033.37,1220.4 1010.23,1197.27 1008.45,1197.27
NetC10_1 on Top Layer "TOP_LAYER_NETC10_2_P036" (solid, remove dead copper, pour order 36): 1198.7,1210 1570,1210 1570,1130 1199.82,1130 1189.82,1140 1198.7,1148.88
USB+ on Top Layer "USB+_L01_P100" (solid, remove dead copper, pour order 100): 310,1090 430,1090 430,1050 431.86,1051.86 507.78,1051.86 507.78,1067.78 560,1120 560,1170 430,1170 370,1110 310,1110
GND on Top Layer "GND_L01_P104" (solid, remove dead copper, pour order 104): 280,980 280,1120 370,1120 433.9,1183.9 1243.9,1183.9 1250,1190 1250,1490 968.64,1490 958.74,1480.1 958.74,1381.57 381.57,1381.57 200,1200 200,890 210,880 370,880 370,980
VSS on Bottom Layer "VSS_L02_P124" (solid, remove dead copper, pour order 124): 1680,1220 1680,970 1930,970 1930,1215.7 1684.3,1215.7
GND on Bottom Layer "GND_L02_P114" (solid, remove dead copper, pour order 114): 1310,290 1310,1770 1320,1780 220,1780 220,300 230,290 320,290

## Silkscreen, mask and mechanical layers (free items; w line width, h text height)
Top Overlay:
  lines w3: 1240,660 1250,660 ; 380,660 380,670 380,680 380,1550 380,1650 1270,1650 1270,660 380,660 ; 1680,960 1930,960 1930,1220 1680,1220 1680,960
  lines w10: 260,1650 360,1650 ; 270,670 370,670 ; 270,1600 310,1640 ; 280,720 320,680 360,720 ; 310,1480 310,1640 ; 320,670 320,870 ; 350,1600 310,1640 ; 380,1710 380,1810 ; 420,1720 380,1760 ; 420,1800 380,1760 ; 510,1760 380,1760 ; 1050,1760 1250,1760 ; 1210,1720 1250,1760 ; 1210,1800 1250,1760 ; 1260,1710 1260,1810 ; 1630,850 1700,850 ; 1670,810 1710,850 1670,890 ; 1710,800 1710,900 ; 1920,800 1920,900 ; 1940,850 2010,850 ; 1970,810 1930,850 1970,890 ; 2040,960 2140,960 ; 2040,1210 2140,1210 ; 2050,910 2090,950 2130,910 ; 2050,1260 2090,1220 ; 2090,870 2090,940 ; 2090,1290 2090,1220 ; 2130,1260 2090,1220
  text "21.8mm" at 910,1750 h40
  text "ChargingCase" at 480,1570 h40
  text "earbud" at 1680,1340 h40
  text "26mm" at 330,1320 h40 r90
  text "5.8mm" at 2100,1030 h40 r90
  text "5.6mm" at 1760,830 h40
  text "TIDA-050007 E1" at 1570,430 h72.83
M1 Board Outline:
  the board outline again, w10
M2 Board Dimensions:
  rectangle: 0,-275 125,-150
  rectangle: 125,-400 500,-275
  lines w7: 0,-275 1000,-275 ; 125,-400 125,-150 ; 250,-400 250,-150 ; 500,-400 500,-150 ; 750,-400 750,-150 ; 0,-400 1000,-400 1000,-150 0,-150 0,-400
  text ".Layer_Name" at 577,-858.49 h20
M3 3D STEP Top:
  text ".Layer_Name" at 577,-858.49 h20
M4 3D STEP Bottom:
  text ".Layer_Name" at 577,-858.49 h20
M5 Assembly Top:
  lines w10: -292,-930.17 6308,-930.17 ; -292,-726.83 6310,-726.83 ; -292,-523.5 -292,-1133.5 3713,-1133.5 6310,-1133.5 6310,-523.5 -291.5,-523.5 -291.5,-1133.5 1284,-1133.5 ; 2173,-1133.5 2173,-523.5 ; 3440,-726.83 3440,-523.5 ; 4280,-726.83 4280,-523.5 ; 4902,-1140 4902,-937.17
  text "COMPONENTS MARKED 'DNP' SHOULD NOT BE POPULATED." at 1153.5,-318.5 h20
  text "ASSEMBLY VARIANT:" at 1153,-434 h20
  text ".VariantName" at 2189,-434 h20
  text "PCB VIEWED FROM TOP SIDE" at -228.5,-655.67 h20
  text "BOARD #:" at 2248,-655.67 h20
  text ".PRJ_Number" at 2793.5,-655.67 h20
  text "REV:" at 3638,-655.67 h20
  text ".PCB_Rev" at 3929.5,-655.67 h20
  text "SVN REV:" at 4476,-655.67 h20
  text ".VersionControl_RevNumber" at 4982,-655.67 h20
  text "TID #:" at 2248,-859 h20
  text ".TID" at 2793.5,-859 h20
  text "PLOT NAME =" at -228.5,-1064.34 h20
  text ".plot_File_Name" at 577,-1064.34 h20
  text "GENERATED    :" at 2250,-1064.34 h20
  text ".Print_Date" at 3119.5,-1064.34 h20
  text ".Print_Time" at 3848.5,-1064.34 h20
  text "TEXAS INSTRUMENTS" at 5113,-1064.34 h20
M6 Assembly Bottom:
  lines w10: -292.5,-727.33 6309.5,-727.33 ; -290.5,-930.67 6309.5,-930.67 ; 1115.5,-1140.5 1115.5,-937.67 ; 1737.5,-727.33 1737.5,-524 ; 2577.5,-727.33 2577.5,-524 ; 3844.5,-1134 3844.5,-524 ; 4733.5,-1134 6309,-1134 6309,-524 -292.5,-524 -292.5,-1134 2304.5,-1134 6309.5,-1134 6309.5,-524
  text "COMPONENTS MARKED 'DNP' SHOULD NOT BE POPULATED." at 6102,-318 h20
  text ".VariantName" at 5058,-434 h20
  text "ASSEMBLY VARIANT:" at 6097,-434 h20
  text ".VersionControl_RevNumber" at 1035.5,-656.17 h20
  text "SVN REV:" at 1541.5,-656.17 h20
  text ".PCB_Rev" at 2088,-656.17 h20
  text "REV:" at 2379.5,-656.17 h20
  text ".PRJ_Number" at 3224,-656.17 h20
  text "BOARD #:" at 3769.5,-656.17 h20
  text "PCB VIEWED FROM BOTTOM SIDE" at 6246,-656.17 h20
  text ".TID" at 3224,-859.5 h20
  text "TID #:" at 3769.5,-859.5 h20
  text "TEXAS INSTRUMENTS" at 904.5,-1064.84 h20
  text ".Print_Time" at 2169,-1064.84 h20
  text ".Print_Date" at 2898,-1064.84 h20
  text "GENERATED    :" at 3767.5,-1064.84 h20
  text ".plot_File_Name" at 5440.5,-1064.84 h20
  text "PLOT NAME =" at 6246,-1064.84 h20
M9 Title Sheet:
  drawing of 57 lines, arcs and shapes, not listed
  text "1" at 739.84,8036.5 h25
  text "2" at 3235.5,8036.5 h25
  text "3" at 5724.84,8036.5 h25
  text "4" at 8231.51,8036.5 h25
  text "5" at 10730.5,8036.5 h25
  text "6" at 13235.5,8036.5 h25
  text "A" at -416.5,6893.5 h25
  text "A" at 14383.5,6893.5 h25
  text "B" at -416.5,4513.5 h25
  text "B" at 14383.5,4513.5 h25
  text "C" at -416.5,2138.5 h25
  text "C" at 14383.5,2138.5 h25
  text "PROJECT TITLE:" at 11343.5,277.5 h20
  text ".PRJ_Title" at 11393.5,144.17 h25
  text "DESIGNED FOR:" at 11343.5,-23.5 h20
  text ".PRJ_Customer" at 11393.5,-163.5 h25
  text "D" at -416.5,-231.5 h25
  text "D" at 14383.5,-231.5 h25
  text "FILE NAME:" at 11343.5,-323.5 h20
  text ".PCB_File_Name_No_Path" at 11393.5,-443.5 h25
  text "Texas Instruments (TI) and/or its licensors do not warrant the accuracy or completeness of this specification" at 6374,-605.34 h25
  text "ENGINEER:" at 11343.5,-613.5 h20
  text "LAYOUT BY:" at 12848.5,-613.5 h20
  text "or any information contained therein. TI and/or its licensors do not warrant that this design will meet" at 6329.01,-718 h25
  text ".PRJ_Engineer" at 11393.5,-768.49 h25
  text ".PCB_Layout" at 12899,-768.49 h25
  text "the specifications, will be suitable for your application or fit for any particular purpose, or will operate in" at 6329.01,-830.67 h25
  text ".Layer_Name" at 577,-858.49 h20
  text "ALTIUM DESIGNER VERSION:" at 12848.5,-923.5 h20
  text "an implementation. TI and/or its licensors do not warrant that the design is production worthy. You should" at 6329.01,-943.33 h25
  text "completely validate and test your design implementation to confirm the system functionality for your application." at 6374,-1056 h25
  text ".print_Scale" at 11393.5,-1056.83 h25
  text ".Application_BuildNumber" at 12899,-1056.83 h25
  text "1" at 739.84,-1263.5 h25
  text "2" at 3235.5,-1263.5 h25
  text "3" at 5724.84,-1263.5 h25
  text "4" at 8231.51,-1263.5 h25
  text "5" at 10730.5,-1263.5 h25
  text "6" at 13235.5,-1263.5 h25
M10 Fab Notes:
  drawing of 189 lines, arcs and shapes, not listed
  text "DESIGN INFORMATION" at 12382.02,6356.17 h20
  text "MIN. TRACK WIDTH:" at 11737.46,6224.05 h20
  text "6" at 12833.7,6224.05 h20
  text "MIL" at 12988.46,6224.05 h20
  text "MIN. CLEARANCE:" at 11737.46,6099.92 h20
  text "0.2" at 12773.7,6099.93 h20
  text "mm" at 12988.46,6099.92 h20
  text "MIN. VIA PAD SIZE:" at 11737.46,5975.8 h20
  text "8" at 12803.71,5975.8 h20
  text "MIL" at 12988.46,5975.8 h20
  text "0.05mm (2MIL)" at 12432.46,5845.9 h20
  text "MINIMUM ANNULAR RING" at 11408.23,5837.67 h20
  text "EXTERNAL" at 13140.46,5837.67 h20
  text "PER" at 11608.23,5727.55 h20
  text "IPC-D-275 CLASS 2 LEVEL C" at 11828.23,5727.54 h20
  text "MIL, HOLES" at 13316.46,5627.07 h20
  text "+/-" at 12924,5618.48 h20
  text "+/-" at 13778,5618.48 h20
  text "REGISTRATION TOLERANCES:" at 11408.23,5617.42 h20
  text "METAL" at 12608,5617.42 h20
  text "5" at 13184.2,5617.42 h20
  text "3" at 14017.2,5617.42 h20
  text "MIL" at 14133.46,5617.42 h20
  text "HOLE SIZE TOLERANCE (UNLESS OTHERWISE SPECIFIED):" at 11408.23,5519.1 h20
  text "+/-" at 13778,5516.23 h20
  text "3" at 14017.2,5515.17 h20
  text "MIL" at 14133.46,5515.17 h20
  text "MATERIAL:" at 11333.46,5377.52 h20
  text "FR-4 High Tg" at 12319.9,5249 h20
  text "X" at 12175.46,5241.01 h20
  text "FR-408" at 11754.46,5236.49 h20
  text "OTHER" at 13242.46,5236.49 h20
  text "62 MIL (1.6mm) +/-10%" at 12074.56,5093.46 h20
  text "X" at 11954.46,5091.01 h20
  text "THICKNESS:" at 11408.23,5085.24 h20
  text "OTHER" at 13359.46,5085.24 h20
  text "TOLERANCE:" at 11408.23,4946.92 h20
  text "X" at 12256.46,4946.92 h20
  text "ANSI IPC-6012 TYPE 3 CLASS 2" at 12434.48,4946.92 h20
  text "OTHER +/-" at 12434.46,4802.73 h20
  text "BOW & TWIST:" at 11408.23,4657.54 h20
  text "X" at 12256.46,4657.54 h20
  text "ANSI IPC-6012 TYPE 3 CLASS 2" at 12434.48,4657.54 h20
  text "OTHER +/-" at 12434.46,4510.85 h20
  text "DRILLING:" at 11333.46,4380.23 h20
  text "NC_DRILL FILES" at 13094.46,4275.04 h20
  text "REFERENCE:" at 11408.23,4271.1 h20
  text "X" at 12065.46,4271.01 h20
  text "AS SHOWN" at 12243.46,4271.1 h20
  text "X" at 12966.46,4271.1 h20
  text "OTHER" at 13392.46,4128.85 h20
  text "PTH COPPER THICKNESS:" at 11407.91,4125.32 h20
  text "X" at 12547.14,4125.32 h20
  text "20-30 um" at 12675.14,4125.32 h20
  text "BOARD FINISH:" at 11333.46,3977.73 h20
  text "SILKSCREEN:" at 11488.68,3867.6 h20
  text "X" at 12446.46,3867.6 h20
  text "TOP" at 12563.46,3867.6 h20
  text "X" at 12956.46,3867.6 h20
  text "BOTTOM" at 13074.46,3867.6 h20
  text "SILKSCREEN COLOR:" at 11488.68,3712.41 h20
  text "X" at 12445.46,3712.41 h20
  text "WHITE" at 12563.46,3712.41 h20
  text "OTHER" at 13074.46,3712.41 h20
  text "X" at 12576.46,3568.96 h20
  text "GREEN" at 12694.46,3568.96 h20
  text "OTHER" at 13312.46,3568.96 h20
  text "SOLDER RESIST COLOR:" at 11488.68,3562.1 h20
  text "X" at 12576.46,3414.71 h20
  text "MATTE" at 12694.46,3414.71 h20
  text "SEMI-GLOSS" at 13312,3414.07 h20
  text "IMMERSION GOLD (ENIG)" at 12394.46,3241.94 h20
  text "ENEPIG" at 13732,3234.72 h20
  text "SURFACE FINISH:" at 11333.46,3233.72 h20
  text "X" at 12216.46,3233.72 h20
  text "IMM. TIN/SILVER OR EQUIV" at 11663,3096.4 h20
  text "OTHER" at 13094.46,3092.47 h20
  text "ARRAY/PANEL:" at 11333.46,2937.09 h20
  text "CUT AND TRIM PER M1 BOARD OUTLINE" at 12394.46,2928.87 h20
  text "N.C. ROUTE" at 12394.46,2792.9 h20
  text "X" at 13082.46,2792.9 h20
  text "V. SCORE" at 13260.46,2792.9 h20
  text "CERTIFICATION:" at 11333.46,2663.77 h20
  text "MATERIALS AND WORKMANSHIP FOR ALL PCBS" at 12058.46,2663.77 h20
  text "TO MEET OR EXCEED THE REQUIREMENTS OF:" at 12058.46,2569.71 h20
  text "X" at 11695.97,2441.08 h20
  text "ANSI IPC-A-600F CLASS ->" at 11823.96,2441.08 h20
  text "X" at 13471.97,2441.08 h20
  text "2" at 13581.96,2441.08 h20
  text "1" at 13266.96,2439.58 h20
  text "3" at 13935.96,2439.58 h20
  text "X" at 12507.97,2293.39 h20
  text "RoHS" at 12635.96,2293.39 h20
  text "OTHER" at 13280.36,2293.39 h20
  text "PER ORDER" at 13677.42,2293.39 h20
  text "ALL BOARDS MUST MEET OR EXCEED UL94-V0 REQUIREMENTS." at 11361,2139.57 h20
  text "PCB MUST BEAR THE UL94V-0 UL REGISTERED MATERIAL ID NUMBER" at 11361,2023.5 h20
  text "ADDITIONAL REQUIREMENTS:" at 11333.46,1854.08 h20
  text "MICROSECTION:" at 11408.23,1746.95 h20
  text "YES" at 12313.96,1746.95 h20
  text "REQUIRED" at 13175.46,1602.62 h20
  text "BARE BOARD ELEC. TEST:" at 11408.23,1599.76 h20
  text "NONE" at 12713.96,1599.76 h20
  text "X" at 13057.46,1599.76 h20
  text "PER ORDER" at 13767.46,1599.76 h20
  text "XX MIL VIAS REQUIRE NON-CONDUCTIVE FILL AND PLANARIZE" at 11576.38,1394.82 h20
  text "XX MIL VIAS REQUIRE CONDUCTIVE FILL AND PLANARIZE" at 11584.38,1290.84 h20
  text "OUTER XX MIL TRACES REQUIRE 50 OHM SINGLE-ENDED IMPEDANCE" at 11583.39,1127.46 h20
  text "LAYER 2 & 3 (INNER LAYERS) XX MIL WIDE, XX MIL SPACE / TRACES REQUIRE 100 OHM DIFFERENTIAL IMPEDANCE" at 11575.39,891.74 h20
  text ".Layer_Name" at 577,-858.49 h20
M11 Gerber Information:
  lines w10: -292,-930.17 6308,-930.17 ; -292,-726.83 6310,-726.83 ; -292,-523.5 -292,-1133.5 3713,-1133.5 6310,-1133.5 6310,-523.5 -291.5,-523.5 -291.5,-1133.5 1284,-1133.5 ; 2173,-1133.5 2173,-523.5 ; 3440,-726.83 3440,-523.5 ; 4280,-726.83 4280,-523.5 ; 4902,-1140 4902,-937.17
  text "ALL ARTWORK VIEWED FROM TOP SIDE" at -228.5,-655.67 h20
  text "BOARD #:" at 2248,-655.67 h20
  text ".PRJ_Number" at 2793.5,-655.67 h20
  text "REV:" at 3638,-655.67 h20
  text ".PCB_Rev" at 3929.5,-655.67 h20
  text "SVN REV:" at 4476,-655.67 h20
  text ".VersionControl_RevNumber" at 4982,-655.67 h20
  text "LAYER NAME =" at -228.5,-858.49 h20
  text "TID #:" at 2248,-859 h20
  text ".TID" at 2793.5,-859 h20
  text "PLOT NAME =" at -228.5,-1064.34 h20
  text ".plot_File_Name" at 577,-1064.34 h20
  text "GENERATED    :" at 2250,-1064.34 h20
  text ".Print_Date" at 3119.5,-1064.34 h20
  text ".Print_Time" at 3848.5,-1064.34 h20
  text "TEXAS INSTRUMENTS" at 5113,-1064.34 h20
M12 Stackup:
  drawing of 198 lines, arcs and shapes, not listed
  text "Layer" at 9757.84,7910 h20
  text "Name" at 9907.81,7910 h20
  text "Material" at 10231.06,7910 h20
  text "Thickness" at 10530.98,7910 h20
  text "Constant" at 10760.93,7910 h20
  text "Board Layer Stack" at 10964.22,7910 h20
  text "1" at 9757.84,7870 h20
  text "Top Overlay" at 9907.81,7870 h20
  text "2" at 9757.84,7830 h20
  text "Top Solder" at 9907.81,7830 h20
  text "Solder Resist" at 10231.06,7830 h20
  text "0.40mil" at 10530.98,7830 h20
  text "3.5" at 10760.93,7830 h20
  text "3" at 9757.84,7790 h20
  text "Top Layer" at 9907.81,7790 h20
  text "Copper" at 10231.06,7790 h20
  text "1.40mil" at 10530.98,7790 h20
  text "4" at 9757.84,7750 h20
  text "Dielectric1" at 9907.81,7750 h20
  text "FR-4" at 10231.06,7750 h20
  text "59.20mil" at 10530.98,7750 h20
  text "4.8" at 10760.93,7750 h20
  text "5" at 9757.84,7710 h20
  text "Bottom Layer" at 9907.81,7710 h20
  text "Copper" at 10231.06,7710 h20
  text "1.40mil" at 10530.98,7710 h20
  text "6" at 9757.84,7670 h20
  text "Bottom Solder" at 9907.81,7670 h20
  text "Solder Resist" at 10231.06,7670 h20
  text "0.40mil" at 10530.98,7670 h20
  text "3.5" at 10760.93,7670 h20
  text "7" at 9757.84,7630 h20
  text "Bottom Overlay" at 9907.81,7630 h20
  text ".Layer_Name" at 577,-858.49 h20
M13 Component Bodies Top:
  text ".Layer_Name" at 577,-858.49 h20
M14 Component Bodies Bottom:
  text ".Layer_Name" at 577,-858.49 h20
M15 Courtyards Top:
  text ".Layer_Name" at 577,-858.49 h20
M16 Courtyards Bottom:
  text ".Layer_Name" at 577,-858.49 h20
M17 Embedded Cavity:
  text ".Layer_Name" at 577,-858.49 h20
M18 Embedded Assembly:
  text ".Layer_Name" at 577,-858.49 h20
M19 Embedded Keepout:
  text ".Layer_Name" at 577,-858.49 h20

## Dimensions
0,-400 to 1000,-400 on M2 Board Dimensions
0,0 to 180,2230 on M2 Board Dimensions
0,0 to 2410,0 on M2 Board Dimensions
